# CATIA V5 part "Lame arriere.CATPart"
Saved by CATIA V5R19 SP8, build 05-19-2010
Part number: Lame arrière
Bounding box of the stored display mesh (mm): x 0 to 5, y -200 to 200, z 0 to 15
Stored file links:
  G:\EU_thinkMotion\CFAO_2010\MMS_groupe2\MMS_groupe2\A reprendre\rbouchet\rbouchet_Catia\Lame arriere.CATPart
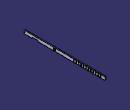
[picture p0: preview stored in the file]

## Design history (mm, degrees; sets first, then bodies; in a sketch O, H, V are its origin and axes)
Body1 (main body)
  Sketch1 on yz-plane, origin (0, 0, 0), H (0, 1, 0), V (0, 0, 1)
    point P1 (-200, 0)
    line L1 (-200, 0) -> (200, 0)
    line L2 (200, 0) -> (200, 15)
    line L3 (200, 15) -> (-200, 15)
    line L4 (-200, 15) -> (-200, 0)
    length L1 = 400
    length L2 = 15
    distance V L4 = 200
    coincidence: P1 H
    horizontal: L1 H, L3 H
    vertical: L2 V, L4 V
  Pad1: profile Sketch1, direction (1, 0, 0), length 5
  Sketch2 on end face of Pad1, origin (5, 0, 0), H (0, 1, 0), V (0, 0, 1)
    point P1 (176, 10)
    line L1 (180, 11.5) -> (180, 10)
    point P2 (180, 11.5)
    point P3 (180, 10)
    arc A1 centre (178, 10) radius 2 from (176, 10) to (180, 10) ccw
    point P5 (180, 10)
    line L2 (176, 10) -> (176, 11.5)
    point P6 (176, 10)
    point P7 (176, 11.5)
    arc A2 centre (178, 11.5) radius 2 from (180, 11.5) to (176, 11.5) ccw
    point P8 (178, 11.5)
    point P9 (180, 11.5)
    point P10 (176, 11.5)
    reference intersected line E1 (200, 15) -> (200, 0) from face of Pad1
    reference intersected line E2 (-175, 15) -> (175, 15) from face of Pad1
    length L2 = 1.5
    radius A2 = 2
    radius A1 = 2
    distance E1 L1 = 20
    distance P8 E2 = 3.5
    vertical: L1 V
    tangency: A1 L1, L2 A1, A2 L1, L2 A2
    coincidence: P5 P3, P6 A1, P1 P6, P9 L1, P10 P7, P9 P2
  Pocket1: profile Sketch2, direction (-1, 0, 0), through (limit type 3)
  RectPattern1: of Pocket1, direction 1 instances 2, spacing -6.5, along edge [face of Pad1 from Sketch1.L2 | end face of Pad1], direction 2 instances 12, spacing 12, along edge [face of Pad1 from Sketch1.L3 | end face of Pad1]
  Sketch3 "Esquisse.3" on end face of Pad1, origin (5, 0, 0), H (0, 1, 0), V (0, 0, 1)
    point P1 (-160, 0)
    line L1 (-160, 0) -> (-130, 0)
    line L2 (-130, 0) -> (-130, 5)
    line L3 (-130, 5) -> (-160, 5)
    line L4 (-160, 5) -> (-160, 0)
    line L5 (-200, 10) -> (-195, 10)
    line L6 (-195, 10) -> (-195, 5)
    line L7 (-195, 5) -> (-200, 5)
    line L8 (-200, 5) -> (-200, 10)
    reference projected line E1 (-200, 15) -> (-200, 0) from edge [face of Pad1 from Sketch1.L4 | end face of Pad1]
    reference projected line E2 (-200, 15) -> (-200, 0) from edge [face of Pad1 from Sketch1.L4 | end face of Pad1]
    reference projected line E3 (200, 15) -> (-200, 15) from edge [face of Pad1 from Sketch1.L3 | end face of Pad1]
    length L7 = 5
    distance E2 L4 = 40
    length L1 = 30
    length L2 = 5
    distance L5 E3 = 5
    length L6 = 5
    coincidence: P1 H, L8 E1
    horizontal: L1 H, L3 H, L5 H, L7 H
    vertical: L2 V, L4 V, L6 V, L8 V
  Pocket2: profile Sketch3, direction (-1, 0, 0), through (limit type 3)
  Sketch4 "Esquisse.4" on end face of Pad1, origin (5, -24.6916, 7.88), H (0, 1, 0), V (0, 0, 1)
    point P1 (-25.3084, -0.38)
    reference projected line E1 (224.6916, 7.12) -> (-175.3084, 7.12) from edge [face of Pad1 from Sketch1.L3 | end face of Pad1]
    reference projected line E2 (-175.3084, 7.12) -> (-175.3084, -7.88) from edge [face of Pad1 from Sketch1.L4 | end face of Pad1]
    distance P1 E1 = 7.5
    distance P1 E2 = 150
  Hole1: placed by Sketch4, at (5, -50, 7.5) direction (-1, 0, 0), diameter 8, through (limit type 3)
  Sketch5 "Esquisse.5" on end face of Pad1, origin (5, -59.8292, 8.1976), H (0, 1, 0), V (0, 0, 1)
    point P1 (9.8292, -0.6976)
    reference projected line E1 (259.8292, 6.8024) -> (-140.1708, 6.8024) from edge [face of Pad1 from Sketch1.L3 | end face of Pad1]
    reference projected line E2 (-140.1708, 6.8024) -> (-140.1708, -8.1976) from edge [face of Pad1 from Sketch1.L4 | end face of Pad1]
    distance P1 E1 = 7.5
    distance P1 E2 = 150
  Hole2: placed by Sketch5, at (5, -50, 7.5) direction (-1, 0, 0), diameter 12, depth 2
  Fillet1: radius 2, on edge [face of Pad1 from Sketch1.L3 | face of Pad1 from Sketch1.L2]; edge [face of Pad1 from Sketch1.L2 | face of Pad1 from Sketch1.L1]; edge [face of Pad1 from Sketch1.L4 | face of Pad1 from Sketch1.L3]; edge [face of Pad1 from Sketch1.L1 | face of Pad1 from Sketch1.L4]
  Fillet2: radius 1, on edge [face of Pocket2 from Sketch3.L4 | face of Pocket2 from Sketch3.L3]; edge [face of Pocket2 from Sketch3.L3 | face of Pocket2 from Sketch3.L2]; edge [face of Pocket2 from Sketch3.L5 | face of Pocket2 from Sketch3.L6]; edge [face of Pocket2 from Sketch3.L6 | face of Pocket2 from Sketch3.L7]; edge [face of Pad1 from Sketch1.L1 | face of Pocket2 from Sketch3.L4]; edge [face of Pocket2 from Sketch3.L2 | face of Pad1 from Sketch1.L1]; edge [face of Pad1 from Sketch1.L4 | face of Pocket2 from Sketch3.L5]; edge [face of Pocket2 from Sketch3.L7 | face of Pad1 from Sketch1.L4]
